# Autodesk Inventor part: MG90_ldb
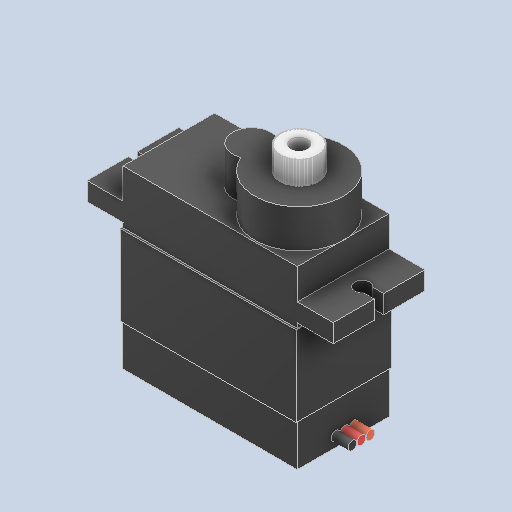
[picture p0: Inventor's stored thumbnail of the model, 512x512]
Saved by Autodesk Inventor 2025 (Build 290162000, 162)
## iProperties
Created: 2019-07
Part Number: MG90_ldb
Material: Alluminio 6061
Document SubType Name: Modeling
Designer: Ryzen5700u
Density: 2.7 g/cm^3
Appearance: Default
Author: Ryzen5700u
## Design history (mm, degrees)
feature "Solido2"
node "Solido1"
